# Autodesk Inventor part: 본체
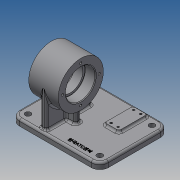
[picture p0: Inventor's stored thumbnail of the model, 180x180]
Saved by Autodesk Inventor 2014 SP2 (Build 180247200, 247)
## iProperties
Created: 2019-09
Part Number: 본체
Material: 알루미늄 6061
Document SubType Name: Modeling
Designer: mduedu
Density: 2.71 g/cm^3
Mass: 561.398 g
Surface Area: 499.749 cm^2
Volume: 207.158 cm^3
Appearance: 기본값
Author: mduedu
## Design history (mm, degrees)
sketch "스케치1"
  geometry: L1 (42, -62)-(-84, -62); L2 (-84, -62)-(-84, 36); L3 (-84, 36)-(42, 36); L4 (42, 36)-(42, -62); 1 further point
  constraints: 8 end point, 2 parallel, 1 horizontal, 1 perpendicular
  dimensions: "d0" = 36 distance from line of L3 point (0, 0); "d1" = 98 distance of L1.end L2.end; "d2" = 42 distance from line of L4 point (0, 0); "d3" = 126 distance of L2.end L3.end
extrude "돌출1" new body sketch "스케치1" distance "d4" = 9; taper "d5" = 0 deg
sketch "스케치2"
  geometry: L1 (0, -62)-(0, 36) reference; C1 r 32 at (59, 0); 1 further point
  constraints: 1 centre point, 1 horizontal alignment
  dimensions: "d6" = 64 diameter of C1; "d7" = 59 distance from line of L1 C1.centre
extrude "돌출2" join sketch "스케치2" stored distance "d8" = 42; taper "d9" = 0 deg
sketch "스케치3"
  geometry: L1 (-17, 4)-(17, 4); L2 (17, 4)-(17, -4); L3 (17, -4)-(-17, -4); L4 (-17, -4)-(-17, 4); L5 (-4, 32)-(4, 32); L6 (4, 32)-(4, -32); L7 (4, -32)-(-4, -32); L8 (-4, -32)-(-4, 32); 5 further points
  constraints: 16 end point, 4 midpoint, 4 parallel, 2 horizontal, 2 horizontal alignment, 2 perpendicular, 2 vertical alignment
  dimensions: "d10" = 8 distance of L5.start L5.end; "d12" = 8 distance of L1.end L2.end; "d13" = 34 distance of L2.end L3.end; "d14" = 64 distance of L5.end L6.end
extrude "돌출3" join sketch "스케치3" stored distance "d15" = 42; taper "d16" = 0 deg
sketch "스케치4"
  geometry: C1 r 32 at (0, 0) reference; C2 r 21 at (0, 0); 1 further point
  constraints: 1 centre point, 1 coincident
  dimensions: "d17" = 42 diameter of C2
extrude "돌출4" cut sketch "스케치4" distance "d18" = 15; taper "d19" = 0 deg
hole "구멍1" diameter "d22" = 36; stored, may be unused: countersink angle "d26" = 90 deg, drill point angle "d28" = 118 deg; dims "d20" = 10, "d21" = 10, "d23" = 6, "d24" = 4, "d25" = 2, "d27" = 8
fillet "모깎기1" dims "d29" = 0.3
chamfer "모따기1" distance "d30" = 1; stored, may be unused: second distance "d31" = 2, angle "d32" = 45 deg
sketch "스케치5" dims "d33" = 52
  geometry: C1 r 32 at (0, 0) reference; 3 further points
  constraints: 2 vertical alignment, 1 coincident, 2 other
hole "구멍2" sketch "스케치5" at (0, 26) diameter "d34" = 3.242; stored, may be unused: countersink angle "d38" = 90 deg, drill point angle "d40" = 118 deg; dims "d35" = 8, "d36" = 4, "d37" = 2, "d39" = 10
fillet "모깎기2" dims "d44" = 12
sketch "스케치6"
  geometry: L1 (-42, 50)-(-42, -24) reference; L2 (-30, -36)-(72, -36) reference; L3 (84, -24)-(84, 50) reference; L4 (72, 62)-(-30, 62) reference; L5 (17, 4)-(17, -4) reference; L6 (17, -4)-(4, -4) reference; L7 (4, -4)-(4, -32) reference; L8 (4, -32)-(-4, -32) reference; L9 (-4, -32)-(-4, -4) reference; L10 (-4, -4)-(-17, -4) reference; L11 (-17, -4)-(-17, 4) reference; L12 (-17, 4)-(-4, 4) reference; L13 (-4, 4)-(-4, 32) reference; L14 (-4, 32)-(4, 32) reference; L15 (4, 32)-(4, 4) reference; L16 (4, 4)-(17, 4) reference; A1 r 12 centre (-30, 50) between (-30, 62) and (-42, 50) reference; A2 r 12 centre (-30, -24) between (-42, -24) and (-30, -36) reference; A3 r 12 centre (72, -24) between (72, -36) and (84, -24) reference; A4 r 12 centre (72, 50) between (84, 50) and (72, 62) reference; 5 further points
  constraints: 4 coincident
hole "구멍3" sketch "스케치6" at (-30, 50), (72, 50), (72, -24), (-30, -24) diameter "d45" = 8; stored, may be unused: countersink angle "d49" = 90 deg, drill point angle "d51" = 118 deg; dims "d46" = 8, "d47" = 4, "d48" = 2, "d50" = 10
sketch "스케치7"
  geometry: L1 (38, 57)-(58, 57); L2 (58, 57)-(58, 17); L3 (58, 17)-(38, 17); L4 (38, 17)-(38, 57); L5 (72, 62)-(-30, 62) reference; 3 further points
  constraints: 8 end point, 2 midpoint, 2 parallel, 1 horizontal, 1 perpendicular
  dimensions: "d52" = 48 horizontal distance of point (48, 57) point (0, 0); "d53" = 20 distance of L1.start L1.end; "d54" = 40 distance of L1.end L2.end; "d55" = 25 distance from line of point (38, 37) L5
extrude "돌출5" join sketch "스케치7" distance "d56" = 3; taper "d57" = 0 deg
fillet "모깎기3" dims "d58" = 3
fillet "모깎기4" dims "d59" = 3
fillet "모깎기5" dims "d60" = 3
fillet "모깎기6" dims "d61" = 3
fillet "모깎기7" dims "d62" = 3
fillet "모깎기8" dims "d63" = 3
sketch "스케치8"
  geometry: L1 (72, 62)-(58.317, 62) reference; L2 (84, -24)-(84, 50) reference; C1 r 1.5 at (43, 53); C2 r 1.5 at (53, 21); 1 further point
  constraints: 2 centre point, 1 equal radius
  dimensions: "d64" = 3 diameter of C1; "d65" = 9 distance from line of C1.centre L1; "d66" = 32 vertical distance of C2.centre C1.centre; "d67" = 10 horizontal distance of C2.centre C1.centre; "d68" = 31 distance from line of L2 C2.centre
hole "구멍4" sketch "스케치8" at (43, 53), (53, 21) diameter "d69" = 3; stored, may be unused: countersink angle "d73" = 90 deg, drill point angle "d75" = 118 deg; dims "d70" = 8, "d71" = 4, "d72" = 2, "d74" = 6
sketch "스케치9"
  geometry: C1 r 1.5 at (43, 53) reference; C2 r 1.5 at (53, 21) reference; 3 further points
  constraints: 2 horizontal alignment, 2 vertical alignment
hole "구멍5" sketch "스케치9" at (53, 53), (43, 21) diameter "d76" = 3.242; stored, may be unused: countersink angle "d80" = 90 deg, drill point angle "d82" = 118 deg; dims "d77" = 6, "d78" = 4, "d79" = 2, "d81" = 8
sketch "스케치10"
  geometry: L1 (-30, -36)-(72, -36) reference; L2 (84, -24)-(84, 50) reference; 2 further points
  constraints: 1 other
  dimensions: "d83" = 10 distance from line of point (46, -26) L1; "d84" = 38 distance from line of point (46, -26) L2
feature "엠보싱1" sketch "스케치10" dims "d0" = 36, "d1" = 98, "d2" = 42, "d3" = 126, "d10" = 8, "d14" = 64, "d85" = 0.5, "d86" = 0
node "솔리드1"
mirror "대칭1"
pattern_circular "원형 패턴1" dims angle "d42" = 360 deg
mirror "대칭2"
node "투영된 루프1"
